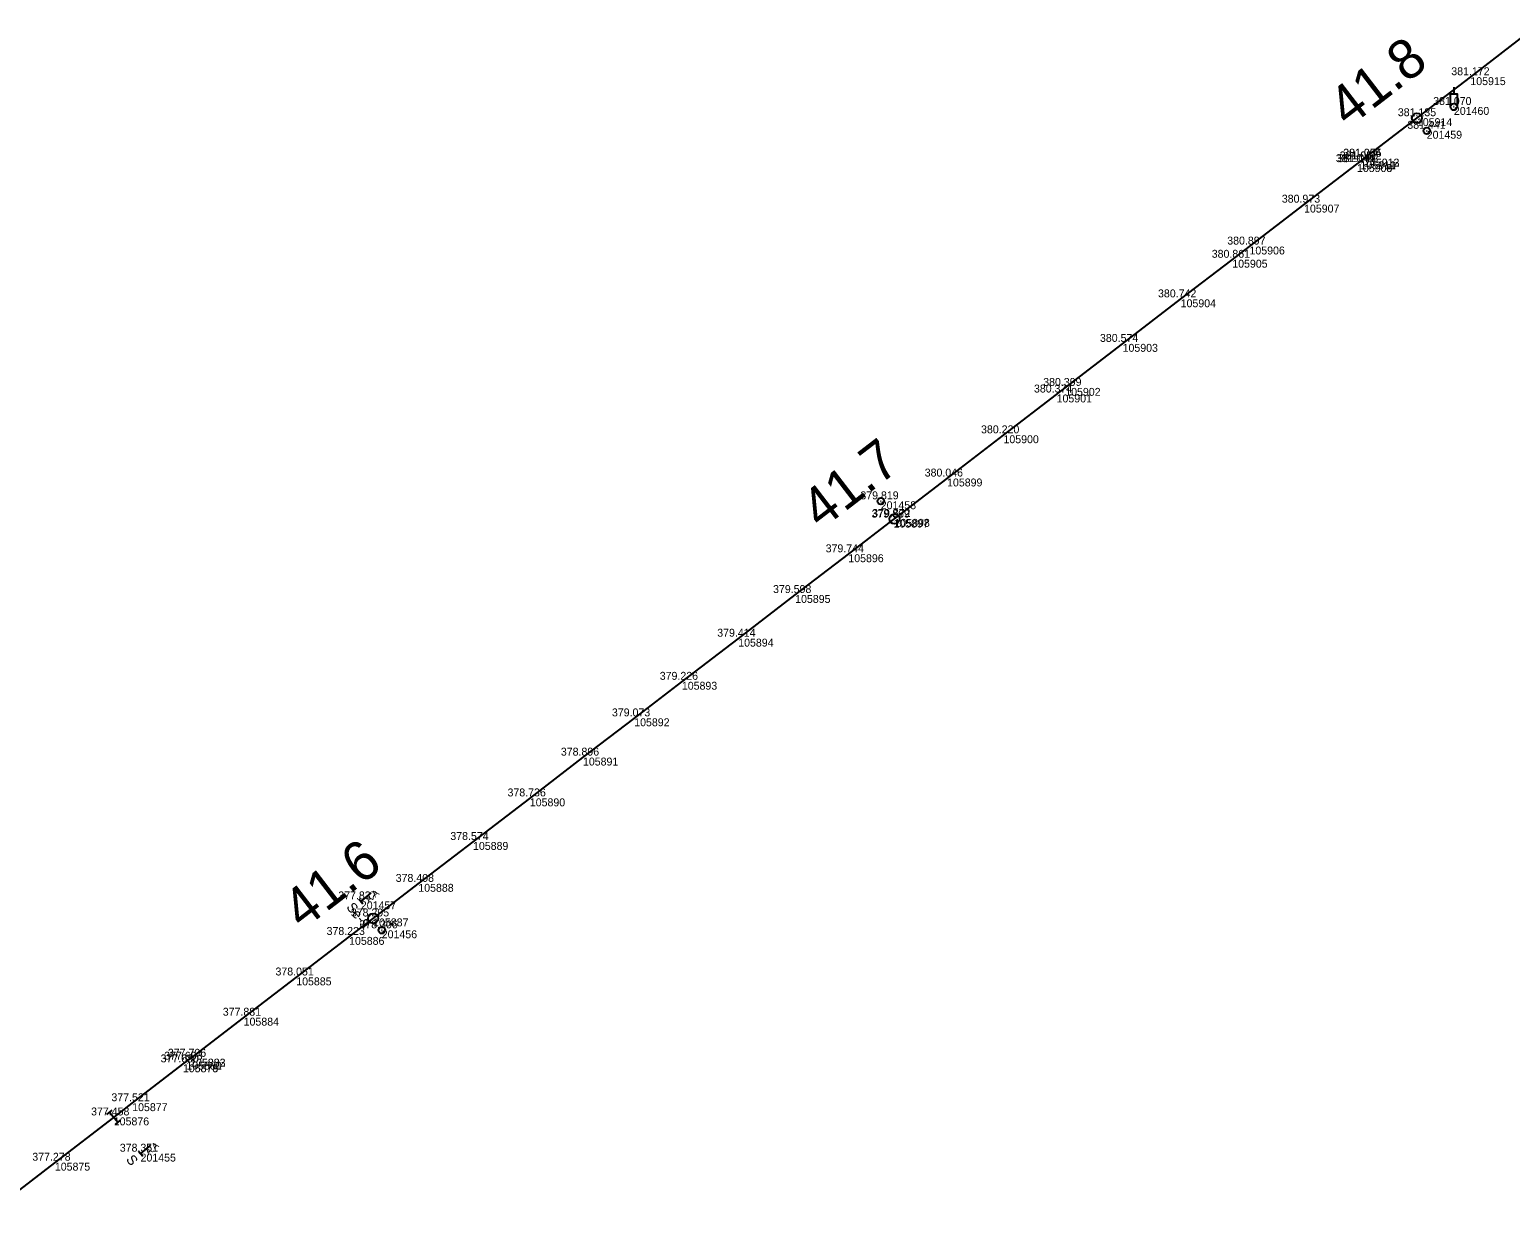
# Model space of a CAD drawing. Extents: x -514522 to -512811, y -1144589 to -1143575.
# Drawn here: x -514094 to -513869.6, y -1144201.4 to -1144022.4 of the extents above; entities that cross this region are included whole.
import ezdxf

# ---------------------------------------------------------------- set-up
doc = ezdxf.new("R2010")
doc.units = 0
for name, color, linetype in [('Vrstva 1', 7, 'Continuous'), ('Vrstva 3', 7, 'Continuous'), ('Vrstva 50', 7, 'Continuous'), ('Vrstva 6', 7, 'Continuous'), ('Vrstva 60', 7, 'Continuous'), ('Vrstva 61', 7, 'Continuous'), ('Vrstva 7', 7, 'Continuous')]:
    doc.layers.add(name, color=color, linetype=linetype)

msp = doc.modelspace()

# ---------------------------------------------------------------- linework, layer by layer
at = {"layer": 'Vrstva 1'}
for p, q in [((-513875.66, -1144029.56), (-513866.28, -1144022.35)), ((-513883.76, -1144035.77), (-513875.66, -1144029.56)), ((-513891.76, -1144041.9), (-513883.76, -1144035.77)), ((-513900.86, -1144048.87), (-513892.84, -1144042.73)), ((-513892.84, -1144042.73), (-513892.31, -1144042.32)), ((-513892.31, -1144042.32), (-513891.76, -1144041.9)), ((-513909.13, -1144055.22), (-513900.86, -1144048.87)), ((-513911.74, -1144057.22), (-513909.13, -1144055.22)), ((-513919.56, -1144063.22), (-513911.74, -1144057.22)), ((-513928.36, -1144069.97), (-513919.56, -1144063.22)), ((-513937.05, -1144076.64), (-513928.36, -1144069.97)), ((-513938.36, -1144077.65), (-513937.05, -1144076.64)), ((-513946.41, -1144083.82), (-513938.36, -1144077.65)), ((-513954.96, -1144090.37), (-513946.41, -1144083.82)), ((-513962.93, -1144096.49), (-513954.96, -1144090.37)), ((-513969.92, -1144101.85), (-513963.08, -1144096.6)), ((-513963.08, -1144096.6), (-513962.93, -1144096.49)), ((-513977.98, -1144108.02), (-513969.92, -1144101.85)), ((-513986.61, -1144114.64), (-513977.98, -1144108.02)), ((-513995.15, -1144121.17), (-513986.61, -1144114.64)), ((-514002.37, -1144126.71), (-513995.15, -1144121.17)), ((-514010.14, -1144132.66), (-514002.37, -1144126.71)), ((-514018.19, -1144138.84), (-514010.14, -1144132.66)), ((-514026.8, -1144145.44), (-514018.19, -1144138.84)), ((-514035.09, -1144151.79), (-514026.8, -1144145.44)), ((-514041.94, -1144157.03), (-514035.09, -1144151.79)), ((-514045.58, -1144159.83), (-514041.94, -1144157.03)), ((-514053.59, -1144165.97), (-514045.58, -1144159.83)), ((-514061.56, -1144172.07), (-514053.59, -1144165.97)), ((-514069.67, -1144178.29), (-514061.56, -1144172.07)), ((-514078.45, -1144185.03), (-514070.76, -1144179.13)), ((-514070.76, -1144179.13), (-514069.67, -1144178.29)), ((-514090.17, -1144194.04), (-514081.24, -1144187.18)), ((-514081.24, -1144187.18), (-514078.45, -1144185.03)), ((-514099.77, -1144201.42), (-514090.17, -1144194.04))]:
    msp.add_line(p, q, dxfattribs=at)
at = {"layer": 'Vrstva 3'}
for p, q in [((-514082.27, -1144186.73), (-514081.5, -1144186.09)), ((-514081.88, -1144186.41), (-514080.6, -1144187.95)), ((-514080.98, -1144188.27), (-514080.22, -1144187.62))]:
    msp.add_line(p, q, dxfattribs=at)
at = {"layer": 'Vrstva 50'}
for p, q in [((-513878.15, -1144031.07), (-513878.15, -1144032.07)), ((-513878.1, -1144034.07), (-513878.2, -1144034.07))]:
    msp.add_line(p, q, dxfattribs=at)
msp.add_lwpolyline([(-513878.65, -1144034.07), (-513878.65, -1144032.07), (-513877.64, -1144032.07), (-513877.64, -1144034.07)], dxfattribs=at)
msp.add_circle((-513878.15, -1144034.07), 0.506, dxfattribs=at)
at = {"layer": 'Vrstva 6'}
for p, q in [((-514042.28, -1144153.17), (-514043.8, -1144154.44)), ((-514044.12, -1144154.06), (-514043.48, -1144154.82)), ((-514075.67, -1144191.4), (-514077.18, -1144192.67)), ((-514077.51, -1144192.29), (-514076.86, -1144193.05))]:
    msp.add_line(p, q, dxfattribs=at)
at = {"layer": 'Vrstva 60'}
for p, q in [((-513875.66, -1144029.56), (-513875.66, -1144029.56)), ((-513878.15, -1144034.07), (-513878.15, -1144034.07)), ((-513883.76, -1144035.77), (-513883.76, -1144035.77)), ((-513882.27, -1144037.68), (-513882.27, -1144037.68)), ((-513892.84, -1144042.73), (-513892.84, -1144042.73)), ((-513892.84, -1144042.73), (-513892.84, -1144042.73)), ((-513892.31, -1144042.32), (-513892.31, -1144042.32)), ((-513892.3, -1144042.31), (-513892.3, -1144042.31)), ((-513891.77, -1144041.91), (-513891.77, -1144041.91)), ((-513891.76, -1144041.9), (-513891.76, -1144041.9)), ((-513900.86, -1144048.87), (-513900.86, -1144048.87)), ((-513909.13, -1144055.22), (-513909.13, -1144055.22)), ((-513911.74, -1144057.22), (-513911.74, -1144057.22)), ((-513919.56, -1144063.22), (-513919.56, -1144063.22)), ((-513928.36, -1144069.97), (-513928.36, -1144069.97)), ((-513937.05, -1144076.64), (-513937.05, -1144076.64)), ((-513938.36, -1144077.65), (-513938.36, -1144077.65)), ((-513946.41, -1144083.82), (-513946.41, -1144083.82)), ((-513954.96, -1144090.37), (-513954.96, -1144090.37)), ((-513965.01, -1144093.82), (-513965.01, -1144093.82)), ((-513963.08, -1144096.6), (-513963.08, -1144096.6)), ((-513962.93, -1144096.49), (-513962.93, -1144096.49)), ((-513969.92, -1144101.85), (-513969.92, -1144101.85)), ((-513977.98, -1144108.02), (-513977.98, -1144108.02)), ((-513986.61, -1144114.64), (-513986.61, -1144114.64)), ((-513995.15, -1144121.17), (-513995.15, -1144121.17)), ((-514002.37, -1144126.71), (-514002.37, -1144126.71)), ((-514010.14, -1144132.66), (-514010.14, -1144132.66)), ((-514018.19, -1144138.84), (-514018.19, -1144138.84)), ((-514026.8, -1144145.44), (-514026.8, -1144145.44)), ((-514035.09, -1144151.79), (-514035.09, -1144151.79)), ((-514043.8, -1144154.44), (-514043.8, -1144154.44)), ((-514041.94, -1144157.03), (-514041.94, -1144157.03)), ((-514045.58, -1144159.83), (-514045.58, -1144159.83)), ((-514040.63, -1144158.83), (-514040.63, -1144158.83)), ((-514053.59, -1144165.97), (-514053.59, -1144165.97)), ((-514061.56, -1144172.07), (-514061.56, -1144172.07)), ((-514070.77, -1144179.14), (-514070.77, -1144179.14)), ((-514070.76, -1144179.13), (-514070.76, -1144179.13)), ((-514070.24, -1144178.73), (-514070.24, -1144178.73)), ((-514070.23, -1144178.73), (-514070.23, -1144178.73)), ((-514069.67, -1144178.29), (-514069.67, -1144178.29)), ((-514069.66, -1144178.28), (-514069.66, -1144178.28)), ((-514081.24, -1144187.18), (-514081.24, -1144187.18)), ((-514078.45, -1144185.03), (-514078.45, -1144185.03)), ((-514077.18, -1144192.67), (-514077.18, -1144192.67)), ((-514090.17, -1144194.04), (-514090.17, -1144194.04))]:
    msp.add_line(p, q, dxfattribs=at)
at = {"layer": 'Vrstva 7'}
for p, q in [((-513882.32, -1144037.68), (-513882.22, -1144037.68)), ((-513965.05, -1144093.82), (-513964.96, -1144093.82)), ((-514040.68, -1144158.83), (-514040.58, -1144158.83))]:
    msp.add_line(p, q, dxfattribs=at)
for centre, radius in [((-513883.76, -1144035.77), 0.75), ((-513882.27, -1144037.68), 0.5), ((-513965.01, -1144093.82), 0.5), ((-513962.93, -1144096.49), 0.75), ((-514041.94, -1144157.03), 0.75), ((-514040.63, -1144158.83), 0.5)]:
    msp.add_circle(centre, radius, dxfattribs=at)

# ---------------------------------------------------------------- texts
at = {"layer": 'Vrstva 6'}
for s, height, rotation, p in [('  A A ', 1, 40, (-514043.16, -1144155.21)), ('Se-9', 1.5, 308.4684, (-514046.07, -1144155.35)), ('  A A ', 1, 40, (-514076.54, -1144193.44)), ('S', 1.5, 308.4684, (-514079.46, -1144193.58))]:
    msp.add_text(s, height=height, rotation=rotation, dxfattribs=at).set_placement(p)
at = {"layer": 'Vrstva 60'}
for s, p in [('105915', (-513875.66, -1144030.76)), ('201460', (-513878.15, -1144035.27)), ('105914', (-513883.76, -1144036.97)), ('201459', (-513882.27, -1144038.88)), ('105908', (-513892.84, -1144043.93)), ('105909', (-513892.84, -1144043.93)), ('105910', (-513892.31, -1144043.52)), ('105911', (-513892.3, -1144043.51)), ('105912', (-513891.77, -1144043.11)), ('105913', (-513891.76, -1144043.1)), ('105907', (-513900.86, -1144050.07)), ('105906', (-513909.13, -1144056.42)), ('105905', (-513911.74, -1144058.42)), ('105904', (-513919.56, -1144064.42)), ('105903', (-513928.36, -1144071.17)), ('105902', (-513937.05, -1144077.84)), ('105901', (-513938.36, -1144078.84)), ('105900', (-513946.41, -1144085.02)), ('105899', (-513954.96, -1144091.57)), ('201458', (-513965.01, -1144095.02)), ('105897', (-513963.08, -1144097.8)), ('105898', (-513962.93, -1144097.69)), ('105896', (-513969.92, -1144103.05)), ('105895', (-513977.98, -1144109.22)), ('105894', (-513986.61, -1144115.84)), ('105893', (-513995.15, -1144122.37)), ('105892', (-514002.37, -1144127.91)), ('105891', (-514010.14, -1144133.86)), ('105890', (-514018.19, -1144140.04)), ('105889', (-514026.8, -1144146.64)), ('105888', (-514035.09, -1144152.99)), ('201457', (-514043.8, -1144155.64)), ('105887', (-514041.94, -1144158.23)), ('105886', (-514045.58, -1144161.03)), ('201456', (-514040.63, -1144160.03)), ('105885', (-514053.59, -1144167.17)), ('105884', (-514061.56, -1144173.27)), ('105878', (-514070.77, -1144180.34)), ('105879', (-514070.76, -1144180.33)), ('105880', (-514070.24, -1144179.93)), ('105881', (-514070.23, -1144179.93)), ('105882', (-514069.67, -1144179.49)), ('105883', (-514069.66, -1144179.48)), ('105876', (-514081.24, -1144188.38)), ('105877', (-514078.45, -1144186.23)), ('201455', (-514077.18, -1144193.87)), ('105875', (-514090.17, -1144195.24))]:
    msp.add_text(s, height=1.2, dxfattribs=at).set_placement(p)
at = {"layer": 'Vrstva 61'}
for s, p in [('381.172', (-513878.55, -1144029.26)), ('381.135', (-513886.65, -1144035.47)), ('381.070', (-513881.29, -1144033.77)), ('381.441', (-513885.21, -1144037.38)), ('381.044', (-513896.04, -1144042.43)), ('381.041', (-513895.75, -1144042.43)), ('381.047', (-513895.47, -1144042.01)), ('381.050', (-513895.44, -1144042.02)), ('381.054', (-513894.93, -1144041.6)), ('381.055', (-513894.91, -1144041.61)), ('380.973', (-513904.23, -1144048.57)), ('380.897', (-513912.5, -1144054.92)), ('380.861', (-513914.85, -1144056.92)), ('380.742', (-513922.99, -1144062.92)), ('380.574', (-513931.79, -1144069.67)), ('380.374', (-513941.79, -1144077.34)), ('380.399', (-513940.39, -1144076.34)), ('380.220', (-513949.81, -1144083.52)), ('380.046', (-513958.35, -1144090.07)), ('379.819', (-513968.1, -1144093.52)), ('379.869', (-513966.4, -1144096.3)), ('379.872', (-513966.31, -1144096.19)), ('379.744', (-513973.36, -1144101.55)), ('379.598', (-513981.33, -1144107.72)), ('379.414', (-513989.79, -1144114.34)), ('379.226', (-513998.5, -1144120.87)), ('379.073', (-514005.75, -1144126.41)), ('378.896', (-514013.49, -1144132.36)), ('378.736', (-514021.57, -1144138.54)), ('378.574', (-514030.24, -1144145.14)), ('378.408', (-514038.52, -1144151.49)), ('377.837', (-514047.22, -1144154.14)), ('378.295', (-514045.32, -1144156.73)), ('378.306', (-514044.01, -1144158.53)), ('378.223', (-514048.99, -1144159.53)), ('378.051', (-514056.74, -1144165.67)), ('377.881', (-514064.72, -1144171.77)), ('377.680', (-514074.15, -1144178.84)), ('377.680', (-514074.14, -1144178.83)), ('377.693', (-514073.6, -1144178.43)), ('377.693', (-514073.59, -1144178.43)), ('377.706', (-514073.05, -1144177.99)), ('377.706', (-514073.04, -1144177.98)), ('377.521', (-514081.6, -1144184.73)), ('377.458', (-514084.68, -1144186.88)), ('378.351', (-514080.33, -1144192.37)), ('377.278', (-514093.59, -1144193.74))]:
    msp.add_text(s, height=1.2, dxfattribs=at).set_placement(p)
at = {"layer": 'Vrstva 7'}
for s, p in [('41.8', (-513894.17, -1144037.32)), ('41.7', (-513974.08, -1144098.23)), ('41.6', (-514052.64, -1144158.88))]:
    msp.add_text(s, height=6, rotation=37.535, dxfattribs=at).set_placement(p)

doc.saveas('drawing.dxf')
